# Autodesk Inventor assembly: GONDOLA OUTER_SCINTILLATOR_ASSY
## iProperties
Shininess: 64.0
Length Units: 11272
Angle Units: 11279
Time Units: 11290
Mass Units: 11286
Length Display Precision: 3
Angle Display Precision: 2
Compacted: True
Part Number: GONDOLA OUTER_SCINTILLATOR_ASSY
Document SubType Name: Assembly
Created: 2004-08
Designer: John Blackburn
Manufacturer: Standard
Standards Organization: Custom
Density: 0.0
Volumn: 0.0
Area: 0.0
PropertySet Name: Model Information
Control State: 0
Master: False
Checked Out: False
Author: John Blackburn
